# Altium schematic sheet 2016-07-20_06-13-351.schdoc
size 419 x 139 mm; SheetNumber: 1; SheetTotal: 1
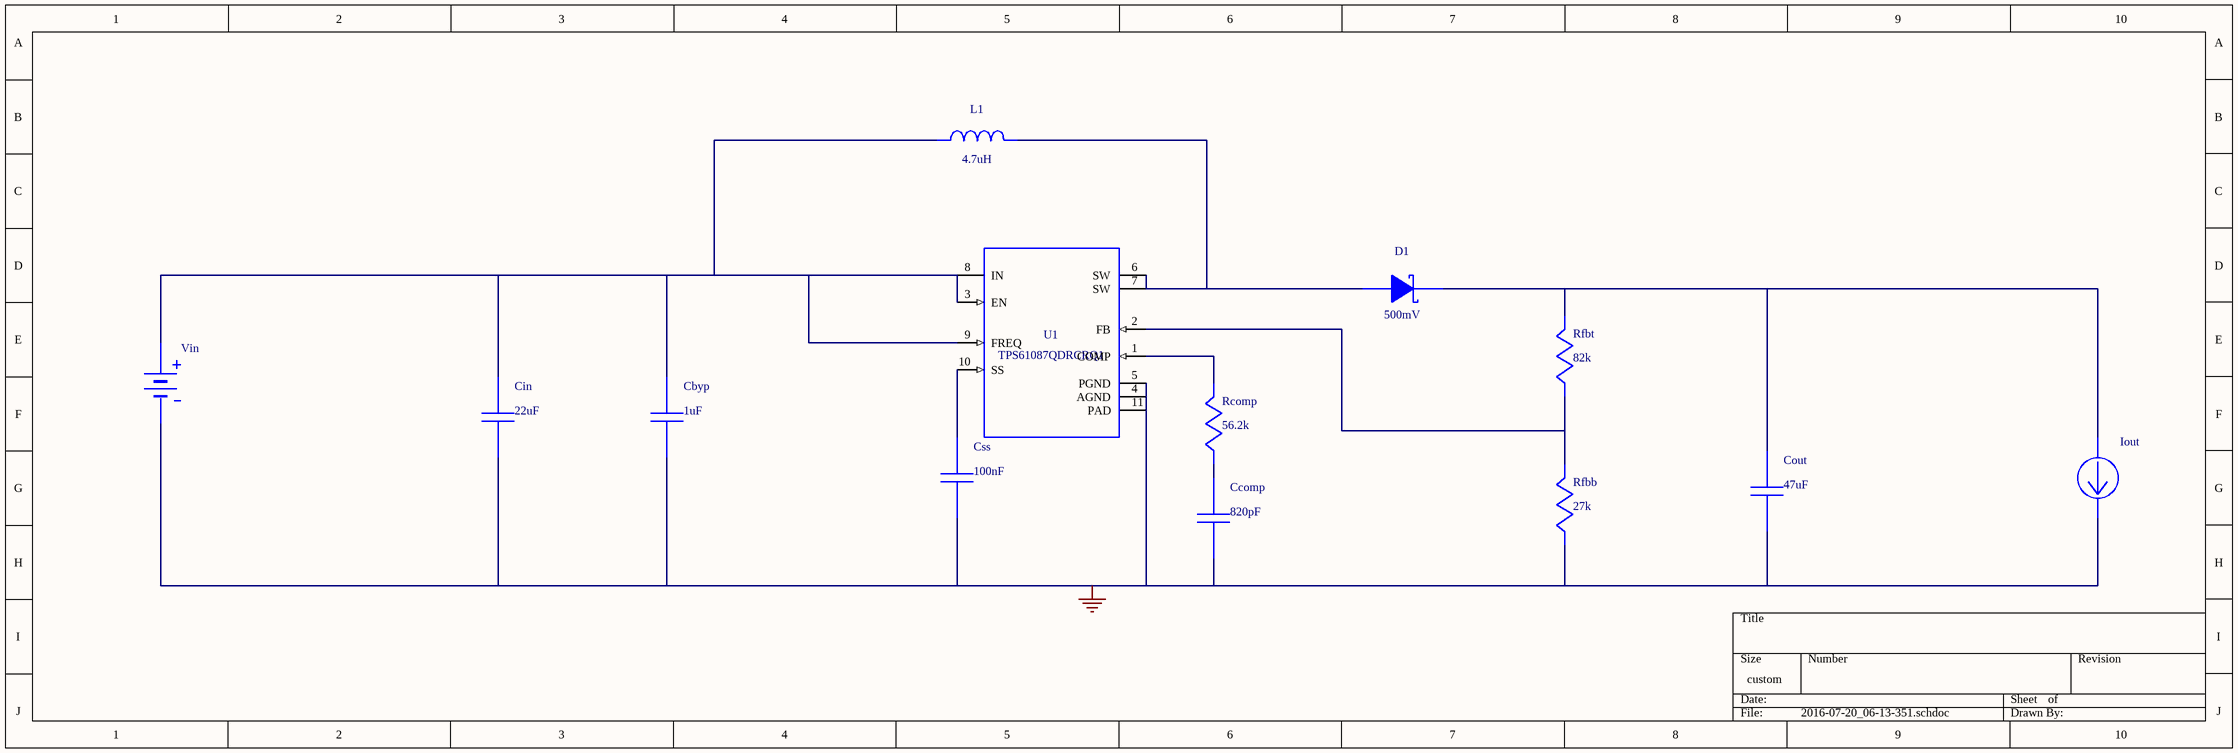
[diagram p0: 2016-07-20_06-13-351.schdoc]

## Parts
Cbyp  value 1uF  (hidden comment: GRM188R61A105KA61D)
Ccomp  value 820pF  (hidden comment: CC0805KRX7R9BB821)
Cin  value 22uF  (hidden comment: LMK212BJ226MG-T)
Cout  value 47uF  (hidden comment: GRM31CR61A476KE15L)
Css  value 100nF  (hidden comment: 08053C104KAT2A)
D1  value 500mV  (hidden comment: B340A-13-F)
Iout  WB_CURRENT_LOAD  (value not drawn)
L1  value 4.7uH  (hidden comment: XFL4020-472MEB)
Rcomp  value 56.2k  (hidden comment: CRCW040256K2FKED)
Rfbb  value 27k  (hidden comment: RC0603FR-0727KL)
Rfbt  value 82k  (hidden comment: RC0603FR-0782KL)
U1  TPS61087QDRCRQ1
Vin  WB_BATTERY  (value not drawn)

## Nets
0: Cbyp.2 Ccomp.2 Cin.2 Cout.2 Css.2 Iout.2(-) Rfbb.2 U1.4(AGND) U1.5(PGND) U1.11(PAD) Vin.2(-)
NetCbyp_1: Cbyp.1 Cin.1 L1.1 U1.3(EN) U1.8(IN) U1.9(FREQ) Vin.1(+)
NetCcomp_1: Ccomp.1 Rcomp.2
NetCout_1: Cout.1 D1.1(K) Iout.1(+) Rfbt.1
NetCss_1: Css.1 U1.10(SS)
NetD1_2: D1.2(A) L1.2 U1.6(SW) U1.7(SW)
NetRcomp_1: Rcomp.1 U1.1(COMP)
NetRfbb_1: Rfbb.1 Rfbt.2 U1.2(FB)

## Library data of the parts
Cbyp = GRM188R61A105KA61D: GRM188R61A105KA6; Manufacturer Name: MuRata
Ccomp = CC0805KRX7R9BB821: CC0805KRX7R9BB82; Manufacturer Name: Yageo America
Cin = LMK212BJ226MG-T: Manufacturer Name: Taiyo Yuden
Cout = GRM31CR61A476KE15L: GRM31CR61A476KE1; Manufacturer Name: MuRata
Css = 08053C104KAT2A: Manufacturer Name: AVX
D1 = B340A-13-F: Manufacturer Name: Diodes Inc.
L1 = XFL4020-472MEB: Manufacturer Name: Coilcraft
Rcomp = CRCW040256K2FKED: Manufacturer Name: Vishay-Dale
Rfbb = RC0603FR-0727KL: Manufacturer Name: Yageo America
Rfbt = RC0603FR-0782KL: Manufacturer Name: Yageo America
U1 = TPS61087QDRCRQ1: Manufacturer Name: Texas Instruments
